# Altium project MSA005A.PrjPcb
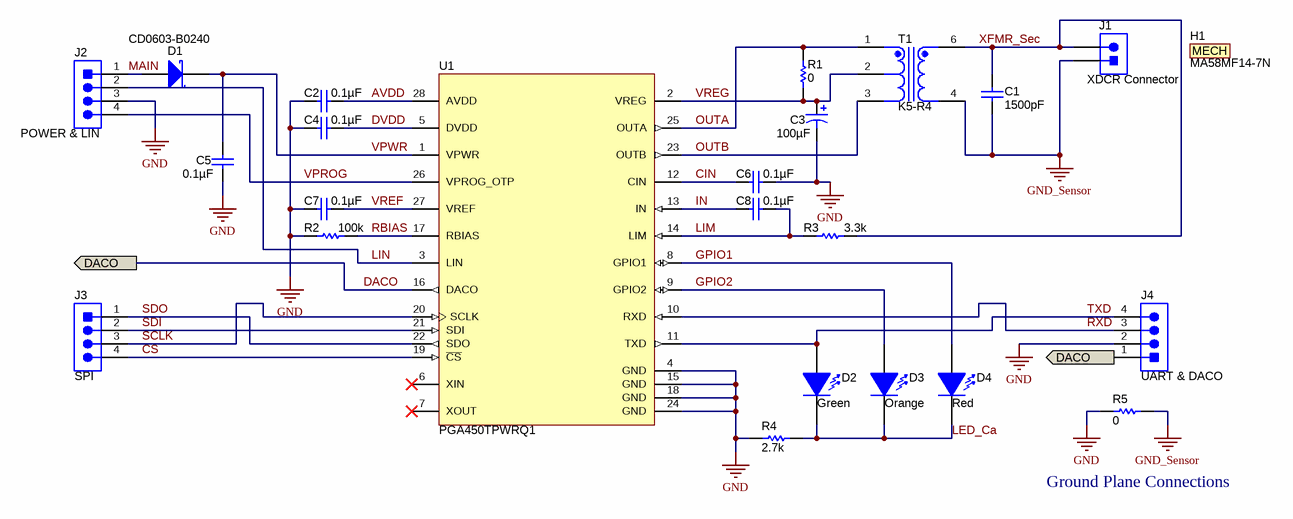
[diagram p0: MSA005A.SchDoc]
CopyrightYear: 2015; PCB_Layout: A. WHITEHEAD; PCB_Rev: A; PRJ_Customer: Public Release; PRJ_Engineer: A. WHITEHEAD; PRJ_Number: MSA005; PRJ_Title: PGA450Q1EVM-S; SCH_Rev: A; TechSupport: http://www.ti.com/support; TID: N/A
2 sheets, 30 parts. Net scope: flat (ports and power ports of the same name join across sheets).
Board file: MSA005A.PcbDoc
Sheets:
  MSA005A.SchDoc
  MSA005A_Hardware.SchDoc

## Sheet MSA005A.SchDoc
size Letter; Date: Not shown in title block; ApprovedBy: Not shown in title block; CheckedBy: Not shown in title block; Author: Not shown in title block; CompanyName: Not shown in title block; DrawnBy: A. WHITEHEAD; Engineer: Not shown in title block; Organization: Not shown in title block; Address1: Not shown in title block; Address2: Not shown in title block; Address3: Not shown in title block; Address4: Not shown in title block; DocumentNumber: 1; Revision: Use project parameter SCH_Rev; SheetNumber: 1; SheetTotal: 2; PageSetup: Record=PageOptions¦CenterHorizontal=True¦CenterVertical=True¦PrintScale=1.00¦XCorrection=1.00¦YCorrection=1.00¦PrintKind=0¦BorderSize=5000000¦LeftOffset=0¦BottomOffset=0¦Orientation=2¦PaperLength=1000¦PaperWidth=1000¦Scale=100¦PaperSource=15¦PrintQuality=600¦MediaType=1¦DitherType=10¦PaperKind=Letter¦PrintScaleMode=1

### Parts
C1  ValueDisplayed: 1500pF  [0805_HV]  (hidden comment: GRM2165C2A152JA01D)
C2  ValueDisplayed: 0.1µF  [0402]  (hidden comment: C1005X7R1H104K050BB)
C3  ValueDisplayed: 100µF  [CAPSMT_62_F80]  (hidden comment: EMVA350ADA101MF80G)
C4  ValueDisplayed: 0.1µF  [0402]  (hidden comment: C1005X7R1H104K050BB)
C5  ValueDisplayed: 0.1µF  [0402]  (hidden comment: C1005X7R1H104K050BB)
C6  ValueDisplayed: 0.1µF  [0402]  (hidden comment: C1005X7R1H104K050BB)
C7  ValueDisplayed: 0.1µF  [0402]  (hidden comment: C1005X7R1H104K050BB)
C8  ValueDisplayed: 0.1µF  [0402]  (hidden comment: C1005X7R1H104K050BB)
D1  CD0603-B0240  [Diode_0603]
D2  value Green  [LED_LTST-C190]  (hidden comment: LTST-C190GKT)
D3  value Orange  [LTST-C191_Orange]  (hidden comment: LTST-C191KFKT)
D4  value Red  [LTST-C191_Red]  (hidden comment: LTST-C191KRKT)
H1  MA58MF14-7N  (mechanical)
J1  XDCR Connector  [CONN_PEC02SAAN]
J2  POWER & LIN  [SULLINS_PEC04SAAN]
J3  SPI  [SULLINS_PEC04SAAN]
J4  UART & DACO  [SULLINS_PEC04SAAN]
R1  ValueDisplayed: 0  [0603]  (hidden comment: MCR03EZPJ000)
R2  ValueDisplayed: 100k  [0603]  (hidden comment: CRCW0603100KJNEA)
R3  ValueDisplayed: 3.3k  [1206]  (hidden comment: CRCW12063K30JNEA)
R4  ValueDisplayed: 2.7k  [0603]  (hidden comment: RC0603JR-072K7L)
R5  ValueDisplayed: 0  [0603]  (hidden comment: MCR03EZPJ000)
T1  K5-R4  [Mitsumi_K5-R4]
U1  PGA450TPWRQ1  [PW0028A_N]

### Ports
DACO

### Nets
GND: C2.2 C3.2(-) C4.1 C5.2 C6.1 C7.2 J2.3 J4.2 R2.1 R4.1 R5.2 U1.4(GND) U1.15(GND) U1.18(GND) U1.24(GND)
GND_Sensor: C1.2 J1.1 R5.1 T1.4
AVDD: C2.1 U1.28(AVDD)
CIN: C6.2 U1.12(CIN)
CS: J3.4 U1.19(~{CS})
DACO: J4.1 U1.16(DACO) ; port DACO
DVDD: C4.2 U1.5(DVDD)
GPIO1: D4.1(A) U1.8(GPIO1)
GPIO2: D3.1(A) U1.9(GPIO2)
IN: C8.2 U1.13(IN)
LED_Ca: D2.2(K) D3.2(K) D4.2(K) R4.2
LIM: C8.1 R3.1 U1.14(LIM)
LIN: J2.2 U1.3(LIN)
MAIN: D1.2(A) J2.1
OUTA: R1.2 T1.1 U1.25(OUTA)
OUTB: T1.3 U1.23(OUTB)
RBIAS: R2.2 U1.17(RBIAS)
RXD: J4.3 U1.10(RXD)
SCLK: J3.3 U1.20(SCLK)
SDI: J3.2 U1.21(SDI)
SDO: J3.1 U1.22(SDO)
TXD: D2.1(A) J4.4 U1.11(TXD)
VPROG: J2.4 U1.26(VPROG_OTP)
VPWR: C5.1 D1.1(K) U1.1(VPWR)
VREF: C7.1 U1.27(VREF)
VREG: C3.1(+) R1.1 T1.2 U1.2(VREG)
XFMR_Sec: C1.1 J1.2 R3.2 T1.6

Not connected (* = marked no-connect by the designer): U1 6(XIN)* 7(XOUT)*

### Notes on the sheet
- Ground Plane Connections

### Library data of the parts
C1 = GRM2165C2A152JA01D: CAP, CERM, 1500 pF, 100 V, +/- 5%, C0G/NP0, 0805; Manufacturer: MuRata; Polarized: N; CompType: Capacitor; Value: 1500pF; U/M: EA; Cap_F: 0.0000000015; Tolerance_%: 5; Value1: Unknown; VDC_V: 100; Value2: 100V; TaMin_C: -55; TaMax_C: 125; Cap_Case: 0805; AEC Category: Q200
C2 C4-C8 = C1005X7R1H104K050BB: CAP, CERM, 0.1 µF, 50 V, +/- 10%, X7R, 0402; Manufacturer: TDK; Polarized: N; CompType: Capacitor; Value: 0.1uF; U/M: EA; Cap_F: 0.0000001; Tolerance_%: 10; Value1: Unknown; VDC_V: 50; Value2: 50V; TaMin_C: -55; TaMax_C: 125; AEC Category: Q200
C3 = EMVA350ADA101MF80G: CAP, AL, 100 µF, 35 V, +/- 20%, SMD; Manufacturer: Chemi-Con; Polarized: Y; CompType: Capacitor; Value: 100uF; U/M: EA; Cap_F: 0.0001; Tolerance_%: 20; Value1: Unknown; VDC_V: 35; Value2: 35V; IRMS_A: 0.12; TaMin_C: -40; TaMax_C: 85; Cap_Case: F80; AEC Category: Q200
D1 = CD0603-B0240: Diode, Schottky, 45 V, 0.2 A, 0603 Diode; Manufacturer: Bourns; U/M: EA; Vf_V: 0.55; Value: 45V; Value1: 0.2A; Value2: 0.55V; Io_A: 0.2; Vr_V: 45; TJmax_C: 125; AEC Category: Q101
D2 = LTST-C190GKT: LED, Green, SMD; Manufacturer: Lite-On; Vf_V: 2.1; Value2: 2.1V; Io_A: 0.02; Power_TotalModule: 0.1; Value1: 0.1W; U/M: EA
D3 = LTST-C191KFKT: LED, Orange, SMD; Manufacturer: Lite-On; Type: AlInGaP; Vf_V: 2; Value2: 2V; Io_A: 0.02; Vr_V: 5; Ir_A: 1e-005; Tjmax_C: 85; Power_TotalModule: 0.075; Value1: 0.075W; Angle: 130; U/M: EA
D4 = LTST-C191KRKT: LED, Red, SMD; Manufacturer: Lite-On; Type: AlInGaP; Vf_V: 2; Value2: 2V; Io_A: 0.02; Vr_V: 5; Ir_A: 1e-005; Tjmax_C: 85; Power_TotalModule: 0.075; Value1: 0.075W; Angle: 130; U/M: EA
H1 = MA58MF14-7N: Ultrasonic Transducer; Manufacturer: MuRata; SymbolCreator: codlsc; CompType: Sensor
J1 = PEC02SAAN: Header, 100mil, 2x1, Tin, TH; Manufacturer: Sullins Connector Solutions; SymbolCreator: a0412235; U/M: EA
J2-J4 = PEC04SAAN: Header, 100mil, 4x1, Tin, TH; Manufacturer: Sullins Connector Solutions; SymbolCreator: a0412235; U/M: EA
R1 R5 = MCR03EZPJ000: RES, 0, 5%, 0.1 W, 0603; Manufacturer: Rohm; CompType: Resistor; Value: 0; Value_Code: 0000; Tolerance_%: 5; Power_W: 0.1; Value2: 0.1W; TempCo: ppm/C; EIA_Code: E24; U/M: EA; AEC Category: Q200; AEC Qualified: N
R2 = CRCW0603100KJNEA: RES, 100 k, 5%, 0.1 W, 0603; Manufacturer: Vishay-Dale; CompType: Resistor; Value: 100k; Res_ohm: 100000; Tolerance_%: 5; Power_W: 0.1; Value2: 0.1W; VDC_V: 75; TempCo: 200 ppm/C; EIA_Code: E24; U/M: EA; AEC Category: Q200
R3 = CRCW12063K30JNEA: RES, 3.3 k, 5%, 0.25 W, 1206; Manufacturer: Vishay-Dale; CompType: Resistor; Value: 3.3k; Res_ohm: 3300; Value_Code: 3k30; Tolerance_%: 5; Power_W: 0.25; Value2: 0.25W; VDC_V: 200; TempCo: 200 ppm/C; EIA_Code: E24; U/M: EA; AEC Category: Q200
R4 = RC0603JR-072K7L: RES, 2.7 k, 5%, 0.1 W, 0603; Manufacturer: Yageo America; CompType: Resistor; Value: 2.7k; Res_ohm: 2700; Value_Code: 2k70; Tolerance_%: 5; Power_W: 0.1; Value2: 0.1W; VDC_V: 50; TempCo: 100 ppm/C; EIA_Code: E24; U/M: EA; AEC Category: Q200
T1 = K5-R4: Transformer, TH; Manufacturer: Mitsumi; SymbolCreator: Altium; U/M: EA
U1 = PGA450TPWRQ1: ULTRASONIC-SENSOR SIGNAL CONDITIONER, PW0028A; Manufacturer: Texas Instruments; SymbolCreator: Altium; CompType: IC; U/M: EA

## Sheet MSA005A_Hardware.SchDoc
size 431 x 279 mm; Date: Not shown in title block; ApprovedBy: Not shown in title block; CheckedBy: Not shown in title block; Author: Not shown in title block; CompanyName: Not shown in title block; DrawnBy: A. WHITEHEAD; Engineer: Not shown in title block; Organization: Not shown in title block; Address1: Not shown in title block; Address2: Not shown in title block; Address3: Not shown in title block; Address4: Not shown in title block; DocumentNumber: 1; Revision: Use project parameter SCH_Rev; SheetNumber: 2; SheetTotal: 2; PageSetup: Record=PageOptions¦CenterHorizontal=True¦CenterVertical=True¦PrintScale=1.00¦XCorrection=1.00¦YCorrection=1.00¦PrintKind=0¦BorderSize=5000000¦LeftOffset=0¦BottomOffset=0¦Orientation=2¦PaperLength=1000¦PaperWidth=1000¦Scale=100¦PaperSource=15¦PrintQuality=600¦MediaType=1¦DitherType=10¦PaperKind=Letter¦PrintScaleMode=1
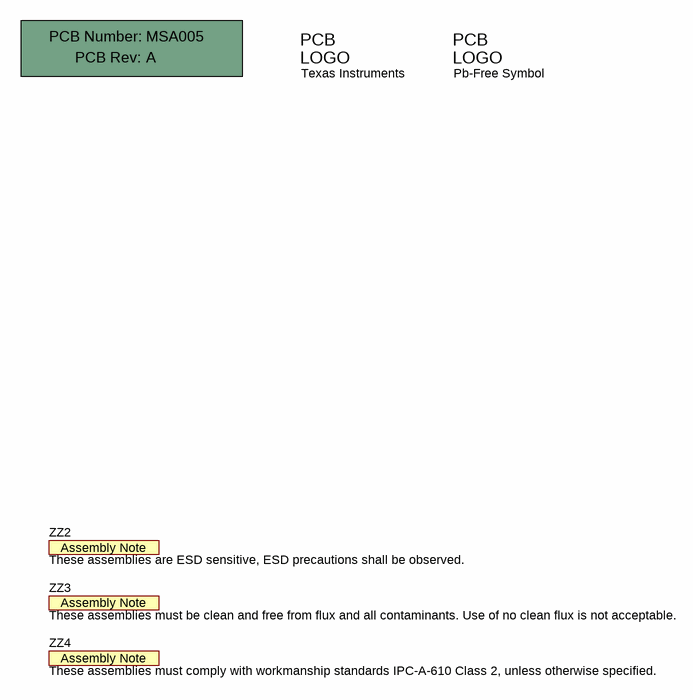
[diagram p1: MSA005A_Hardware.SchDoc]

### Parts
!PCB1  Printed Circuit Board  (value not drawn)  (mechanical)
Logo1  Texas Instruments  [TI_Symbol_Overlay_Small]  (no BOM)
Logo2  Pb-Free Symbol  [Pb-Free_Overlay_Small]  (no BOM)
ZZ2  These assemblies are ESD sensitive, ESD precautions shall be observed.  [AssemblyNote]  (no BOM)
ZZ3  These assemblies must be clean and free from flux and all contaminants. Use of no clean flux is not acceptable.  [AssemblyNote]  (no BOM)
ZZ4  These assemblies must comply with workmanship standards IPC-A-610 Class 2, unless otherwise specified.  [AssemblyNote]  (no BOM)

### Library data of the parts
!PCB1 = PCB: Manufacturer: Any; PartNumber: MSA005; SymbolCreator: a0412235
Logo1 = TI_Logo: Texas Instrument Corporate Signature; SymbolCreator: codlsc
Logo2 = Pb-Free: SymbolCreator: a0412235
ZZ2-ZZ4 = AssemblyNote: SymbolCreator: codlsc

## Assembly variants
001: not fitted D2 J1 R1
002: not fitted D2 J1 J2 J3 J4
